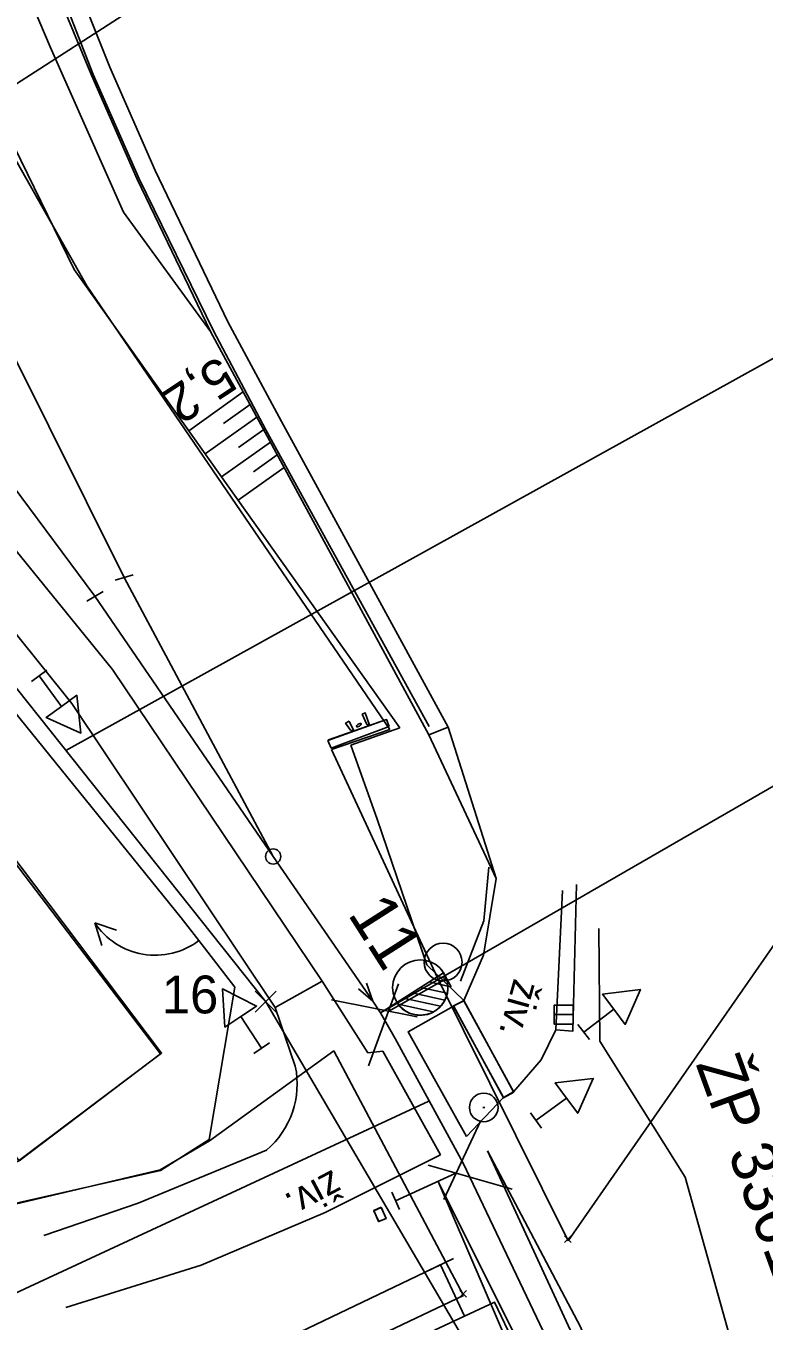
# Model space of a CAD drawing. Extents: x -804166 to -803706, y -1151030 to -1150147.
# Drawn here: x -803897.2 to -803858.2, y -1150515.9 to -1150447.5 of the extents above; entities that cross this region are included whole.
import ezdxf

# ---------------------------------------------------------------- set-up
doc = ezdxf.new("R2010")
doc.units = 0
for name, color, linetype in [('0381KM032-037P - Vrstva 1', 7, 'Continuous'), ('0381KM032-037P - Vrstva 12', 7, 'Continuous'), ('0381KM032-037P - Vrstva 13', 7, 'Continuous'), ('0381KM032-037P - Vrstva 17', 7, 'Continuous'), ('0381KM032-037P - Vrstva 19', 7, 'Continuous'), ('0381KM032-037P - Vrstva 2', 7, 'Continuous'), ('0381KM032-037P - Vrstva 23', 7, 'Continuous'), ('0381KM032-037P - Vrstva 3', 7, 'Continuous'), ('0381KM032-037P - Vrstva 4', 7, 'Continuous'), ('0381KM032-037P - Vrstva 43', 7, 'Continuous'), ('0381KM032-037P - Vrstva 48', 7, 'Continuous'), ('0381KM032-037P - Vrstva 49', 7, 'Continuous'), ('0381KM032-037P - Vrstva 5', 7, 'Continuous'), ('0381KM032-037P - Vrstva 51', 7, 'Continuous'), ('0381KM032-037P - Vrstva 55', 7, 'Continuous'), ('Default', 7, 'Continuous'), ('hran DP - hran DP', 7, 'Continuous'), ('PSR_C2_2_Lomove_body_Vimperk - Vrstva 60', 7, 'Continuous'), ('PSR_C2_2_trasa_Vimperk - Kabelová trasa', 7, 'Continuous'), ('SOPS', 7, 'Continuous'), ('vyt_sit - stávající', 7, 'Continuous')]:
    doc.layers.add(name, color=color, linetype=linetype)

msp = doc.modelspace()

# ---------------------------------------------------------------- linework, layer by layer
at = {"layer": '0381KM032-037P - Vrstva 1'}
msp.add_line((-803901.897, -1150466.329), (-803893.522, -1150477.59), dxfattribs=at)
for points in [[(-804011.14, -1150262.39), (-804005.45, -1150273.41), (-803998.73, -1150284.85), (-803991.51, -1150295.63), (-803978.8, -1150312.77), (-803963.69, -1150332.99), (-803952.21, -1150348.36), (-803946.3, -1150356.39), (-803941.6, -1150363.14), (-803936.71, -1150370.83), (-803932.05, -1150378.84), (-803927.78, -1150386.91), (-803924.06, -1150395.18), (-803920.62, -1150403.65), (-803918.06, -1150410.86), (-803915.07, -1150420.32), (-803912.96, -1150427.25), (-803910.49, -1150435.34), (-803907.334, -1150445.05), (-803903.668, -1150454.381), (-803897.938, -1150464.596), (-803891.973, -1150476.598)], [(-803891.973, -1150476.598), (-803884.106, -1150491.333), (-803878.839, -1150498.97), (-803878.441, -1150499.601)], [(-803893.522, -1150477.59), (-803884.106, -1150491.333), (-803878.839, -1150498.97), (-803878.441, -1150499.601)], [(-803878.441, -1150499.601), (-803877.664, -1150500.946), (-803874.069, -1150507.541)], [(-803874.069, -1150507.541), (-803869.666, -1150516.774), (-803865.801, -1150526.594), (-803862.645, -1150536.71)]]:
    msp.add_lwpolyline(points, dxfattribs=at)
at = {"layer": '0381KM032-037P - Vrstva 12'}
for q in [(-803878.793, -1150510.039), (-803878.397, -1150509.87), (-803878.143, -1150510.457)]:
    msp.add_line((-803878.393, -1150509.855), q, dxfattribs=at)
for points in [[(-803878.788, -1150510.049), (-803878.793, -1150510.039), (-803878.537, -1150510.622), (-803878.523, -1150510.621)], [(-803878.397, -1150509.87), (-803878.788, -1150510.049), (-803878.523, -1150510.621), (-803878.141, -1150510.449), (-803878.397, -1150509.87)], [(-803878.537, -1150510.622), (-803878.143, -1150510.457), (-803878.141, -1150510.449)]]:
    msp.add_lwpolyline(points, dxfattribs=at)
at = {"layer": '0381KM032-037P - Vrstva 13'}
msp.add_lwpolyline([(-803875.883, -1150484.91), (-803874.859, -1150484.495), (-803883.662, -1150468.351), (-803886.496, -1150463.09), (-803890.342, -1150455.103), (-803892.739, -1150449.637), (-803894.892, -1150444.207), (-803895.921, -1150441.276), (-803896.676, -1150438.635), (-803897.147, -1150435.872), (-803897.2, -1150433.432), (-803898.654, -1150433.258), (-803898.54, -1150435.86), (-803897.995, -1150438.863), (-803897.041, -1150441.738), (-803895.987, -1150444.528), (-803893.704, -1150450.064), (-803891.289, -1150455.545), (-803887.412, -1150463.602)], close=True, dxfattribs=at)
at = {"layer": '0381KM032-037P - Vrstva 17'}
msp.add_line((-803888.961, -1150494.568), (-803888.027, -1150495.776), dxfattribs=at)
for points in [[(-803875.87, -1150484.459), (-803884.486, -1150468.8), (-803887.25, -1150463.566), (-803891.192, -1150455.528), (-803893.615, -1150450.032), (-803895.787, -1150444.436), (-803896.9, -1150441.761), (-803897.818, -1150438.885), (-803898.314, -1150435.883), (-803898.256, -1150432.783)], [(-803907.336, -1150471.899), (-803888.961, -1150494.568)], [(-803872.719, -1150491.9), (-803872.971, -1150494.735), (-803874.21, -1150497.92)], [(-803888.027, -1150495.776), (-803886.131, -1150498.244), (-803887.49, -1150506.275), (-803890.053, -1150507.927), (-803899.02, -1150509.954)]]:
    msp.add_lwpolyline(points, dxfattribs=at)
at = {"layer": '0381KM032-037P - Vrstva 19'}
for p, q in [((-803881.212, -1150485.202), (-803878.118, -1150484.104)), ((-803879.404, -1150483.821), (-803879.155, -1150484.356)), ((-803879.155, -1150484.356), (-803879.022, -1150484.392)), ((-803878.118, -1150484.104), (-803877.97, -1150484.474)), ((-803877.97, -1150484.474), (-803881.045, -1150485.616)), ((-803881.045, -1150485.616), (-803881.212, -1150485.202))]:
    msp.add_line(p, q, dxfattribs=at)
for points in [[(-803879.022, -1150484.392), (-803879.242, -1150483.752), (-803879.404, -1150483.821)], [(-803878.118, -1150484.104), (-803878.118, -1150484.104), (-803881.188, -1150485.171), (-803881.212, -1150485.202)], [(-803880.088, -1150484.181), (-803879.836, -1150484.689), (-803880.019, -1150484.664), (-803880.278, -1150484.296), (-803880.088, -1150484.181)]]:
    msp.add_lwpolyline(points, dxfattribs=at)
msp.add_ellipse((-803879.582, -1150484.395), major_axis=(-0.127, -0.08), ratio=0.380929, dxfattribs=at)
at = {"layer": '0381KM032-037P - Vrstva 2'}
for p, q in [((-803878.441, -1150499.601), (-803834.824, -1150474.404)), ((-803892.452, -1150476.741), (-803891.494, -1150476.455)), ((-803891.973, -1150476.598), (-803884.106, -1150491.333)), ((-803893.094, -1150477.331), (-803893.95, -1150477.849)), ((-803877.575, -1150499.045), (-803875.106, -1150497.473)), ((-803875.874, -1150497.962), (-803874.883, -1150498.182)), ((-803875.427, -1150497.677), (-803874.961, -1150497.78)), ((-803877.217, -1150498.817), (-803875.266, -1150499.249)), ((-803876.77, -1150498.532), (-803875.035, -1150498.916)), ((-803876.321, -1150498.247), (-803874.912, -1150498.559)), ((-803877.576, -1150499.046), (-803878.441, -1150499.601)), ((-803877.574, -1150499.046), (-803877.575, -1150499.045)), ((-803877.507, -1150499.136), (-803875.654, -1150499.547))]:
    msp.add_line(p, q, dxfattribs=at)
for points in [[(-803893.522, -1150477.59), (-803884.106, -1150491.333), (-803878.839, -1150498.97), (-803878.441, -1150499.601)], [(-803879.6, -1150498.322), (-803878.839, -1150498.97), (-803879.174, -1150498.028)]]:
    msp.add_lwpolyline(points, dxfattribs=at)
for centre, radius in [((-803884.106, -1150491.333), 0.4), ((-803876.333, -1150498.256), 1.462)]:
    msp.add_circle(centre, radius, dxfattribs=at)
msp.add_arc((-803876.341, -1150498.259), 1.464, 212.53717, 32.49802, dxfattribs=at)
at = {"layer": '0381KM032-037P - Vrstva 23'}
for p, q in [((-803893.152, -1150496.036), (-803893.533, -1150494.83)), ((-803893.533, -1150494.83), (-803893.152, -1150496.036)), ((-803893.533, -1150494.83), (-803892.379, -1150495.228))]:
    msp.add_line(p, q, dxfattribs=at)
msp.add_lwpolyline([(-803897.633, -1150507.469), (-803890, -1150501.72), (-803898.947, -1150489.885)], dxfattribs=at)
msp.add_arc((-803890.335, -1150492.714), 3.834, 213.48969, 307.00957, dxfattribs=at)
at = {"layer": '0381KM032-037P - Vrstva 3'}
msp.add_line((-803903.668, -1150454.381), (-803871.126, -1150433.376), dxfattribs=at)
at = {"layer": '0381KM032-037P - Vrstva 4'}
for p, q in [((-803874.703, -1150498.219), (-803875.193, -1150497.347)), ((-803879.067, -1150502.394), (-803877.487, -1150498.063)), ((-803874.948, -1150497.783), (-803877.999, -1150499.498)), ((-803876.506, -1150499.806), (-803881.027, -1150498.907)), ((-803877.664, -1150500.946), (-803874.069, -1150507.541)), ((-803875.88, -1150504.253), (-803939.777, -1150533.943)), ((-803873.145, -1150505.275), (-803875.086, -1150509.456)), ((-803875.915, -1150507.636), (-803871.486, -1150508.915)), ((-803877.639, -1150509.52), (-803874.454, -1150508.069)), ((-803877.846, -1150509.065), (-803877.432, -1150509.975))]:
    msp.add_line(p, q, dxfattribs=at)
for points in [[(-803872.779, -1150506.875), (-803867.872, -1150516.171), (-803864.004, -1150525.679), (-803860.599, -1150536.286), (-803857.956, -1150547.888), (-803856.113, -1150558.65), (-803855.009, -1150569.422), (-803855.013, -1150580.14), (-803855.681, -1150591.137), (-803857.109, -1150602.102)], [(-803872.779, -1150506.875), (-803868.424, -1150516.34), (-803864.491, -1150525.922), (-803861.191, -1150536.397), (-803858.415, -1150547.949), (-803856.721, -1150558.765), (-803855.706, -1150569.464), (-803855.706, -1150580.041), (-803856.439, -1150591.045), (-803858.016, -1150602.009)], [(-803875.392, -1150508.511), (-803870.942, -1150517.43), (-803867.281, -1150527.019), (-803864.067, -1150537.143), (-803861.546, -1150548.304), (-803859.948, -1150558.943), (-803859.253, -1150569.653), (-803859.085, -1150579.867)], [(-803875.392, -1150508.511), (-803871.454, -1150517.68), (-803867.834, -1150527.236), (-803864.663, -1150537.291), (-803862.152, -1150548.382), (-803860.595, -1150558.999), (-803859.922, -1150569.628), (-803859.947, -1150579.801), (-803860.5, -1150590.58), (-803862.041, -1150601.171)]]:
    msp.add_lwpolyline(points, dxfattribs=at)
at = {"layer": '0381KM032-037P - Vrstva 43'}
for points in [[(-803871.406, -1150503.772), (-803871.943, -1150504.067), (-803874.575, -1150499.234), (-803874.041, -1150498.946), (-803871.406, -1150503.772)], [(-803874.573, -1150499.229), (-803874.026, -1150498.951), (-803871.394, -1150503.78), (-803871.938, -1150504.086), (-803874.573, -1150499.229)], [(-803869.26, -1150499.687), (-803869.26, -1150499.187), (-803868.26, -1150499.187), (-803868.26, -1150500.187), (-803869.26, -1150500.187), (-803869.26, -1150499.687), (-803868.26, -1150499.687)]]:
    msp.add_lwpolyline(points, dxfattribs=at)
msp.add_circle((-803875.129, -1150496.91), 1, dxfattribs=at)
at = {"layer": '0381KM032-037P - Vrstva 48'}
for p, q in [((-803885.686, -1150466.792), (-803888.569, -1150468.841)), ((-803885.327, -1150467.456), (-803886.73, -1150468.454)), ((-803884.967, -1150468.121), (-803887.7, -1150470.063)), ((-803884.607, -1150468.786), (-803885.936, -1150469.73)), ((-803884.248, -1150469.45), (-803886.831, -1150471.286)), ((-803883.888, -1150470.115), (-803885.142, -1150471.006)), ((-803883.529, -1150470.779), (-803885.962, -1150472.509))]:
    msp.add_line(p, q, dxfattribs=at)
at = {"layer": '0381KM032-037P - Vrstva 49'}
for p, q in [((-803880.011, -1150485.455), (-803877.416, -1150484.532)), ((-803875.883, -1150484.91), (-803872.322, -1150492.497)), ((-803868.71, -1150511.374), (-803868.356, -1150511.726)), ((-803868.357, -1150511.373), (-803868.709, -1150511.727)), ((-803874.253, -1150514.268), (-803873.899, -1150514.62)), ((-803873.9, -1150514.267), (-803874.252, -1150514.621))]:
    msp.add_line(p, q, dxfattribs=at)
for points in [[(-803920.94, -1150376.21), (-803910.018, -1150390.511), (-803912.553, -1150396.059), (-803903.866, -1150412.95), (-803903.684, -1150418.644), (-803901.421, -1150428.97), (-803900.537, -1150437.639), (-803895.89, -1150448.56), (-803892.01, -1150457.3), (-803887.412, -1150463.602), (-803875.883, -1150484.91), (-803874.859, -1150484.495), (-803872.322, -1150492.497), (-803872.997, -1150496.546), (-803874.041, -1150498.946)], [(-803877.416, -1150484.532), (-803894.615, -1150460.334), (-803907.648, -1150433.624), (-803908.812, -1150430.908)], [(-803874.041, -1150498.946), (-803875.993, -1150497.05), (-803878.613, -1150489.357), (-803880.011, -1150485.455)], [(-803866.91, -1150495.141), (-803866.848, -1150501.095), (-803862.336, -1150508.281), (-803859.067, -1150519.976)]]:
    msp.add_lwpolyline(points, dxfattribs=at)
at = {"layer": '0381KM032-037P - Vrstva 5'}
for p, q in [((-803875.265, -1150512.897), (-803915.956, -1150532.369)), ((-803874.586, -1150512.578), (-803875.944, -1150513.216))]:
    msp.add_line(p, q, dxfattribs=at)
msp.add_lwpolyline([(-803875.265, -1150512.897), (-803873.991, -1150515.613), (-803875.575, -1150516.356), (-803874.513, -1150518.62), (-803871.345, -1150517.133), (-803872.407, -1150514.87), (-803873.991, -1150515.613)], dxfattribs=at)
at = {"layer": '0381KM032-037P - Vrstva 51'}
for p, q in [((-803896.066, -1150481.493), (-803896.874, -1150482.083)), ((-803881.519, -1150497.913), (-803884.008, -1150499.305)), ((-803879.108, -1150501.711), (-803881.519, -1150497.913)), ((-803884.008, -1150499.305), (-803882.935, -1150502.416)), ((-803868.005, -1150500.208), (-803867.403, -1150501.008)), ((-803885.131, -1150501.736), (-803884.297, -1150501.184)), ((-803870.52, -1150504.875), (-803869.928, -1150505.681))]:
    msp.add_line(p, q, dxfattribs=at)
for points in [[(-803881.519, -1150497.913), (-803892.597, -1150481.46), (-803901.351, -1150470.694), (-803906.021, -1150467.127), (-803910.842, -1150463.746), (-803913.43, -1150460.674), (-803913.908, -1150457.138), (-803915.72, -1150453.288)], [(-803884.008, -1150499.305), (-803894.736, -1150483.244), (-803900.893, -1150475.608)], [(-803896.47, -1150481.788), (-803895.29, -1150483.403), (-803896.098, -1150483.993), (-803894.258, -1150484.816), (-803894.483, -1150482.813), (-803895.29, -1150483.403)], [(-803872.322, -1150492.497), (-803872.997, -1150496.546), (-803874.041, -1150498.946), (-803874.575, -1150499.234), (-803876.979, -1150500.591), (-803873.894, -1150506.131)], [(-803868.09, -1150492.82), (-803868.275, -1150500.556), (-803869.181, -1150500.495), (-803868.824, -1150493.135)], [(-803884.714, -1150501.46), (-803885.817, -1150499.792), (-803884.983, -1150499.24), (-803886.783, -1150498.332), (-803886.651, -1150500.344), (-803885.817, -1150499.792)], [(-803867.704, -1150500.608), (-803866.106, -1150499.406), (-803865.505, -1150500.205), (-803864.707, -1150498.354), (-803866.707, -1150498.607), (-803866.106, -1150499.406)], [(-803869.181, -1150500.495), (-803869.951, -1150502.075), (-803871.406, -1150503.772), (-803871.943, -1150504.067), (-803873.894, -1150506.131)], [(-803875.265, -1150507.099), (-803878.317, -1150501.626), (-803879.108, -1150501.711)], [(-803870.224, -1150505.278), (-803868.612, -1150504.094), (-803868.02, -1150504.899), (-803867.202, -1150503.057), (-803869.205, -1150503.288), (-803868.612, -1150504.094)], [(-803884.454, -1150506.841), (-803891.238, -1150509.65), (-803896.223, -1150511.347)], [(-803895.065, -1150515.152), (-803887.917, -1150512.923), (-803881.363, -1150510.148), (-803875.265, -1150507.099)]]:
    msp.add_lwpolyline(points, dxfattribs=at)
msp.add_ellipse((-803887.406, -1150503.348), major_axis=(0.394, 4.563), ratio=0.996998, start_param=3.930903, end_param=5.00319, dxfattribs=at)
at = {"layer": '0381KM032-037P - Vrstva 55'}
msp.add_lwpolyline([(-803901.34, -1150491.89), (-803905.5, -1150486.41), (-803911.98, -1150477.87), (-803911.71, -1150477.67), (-803912.3, -1150476.91), (-803912.56, -1150477.11), (-803912.92, -1150476.64), (-803914.71, -1150478.01), (-803917.95, -1150480.48), (-803906.42, -1150495.69), (-803897.53, -1150507.41), (-803890.06, -1150501.75), (-803898.96, -1150490.08), (-803901.34, -1150491.89)], dxfattribs=at)
at = {"layer": 'hran DP - hran DP'}
for p, q in [((-803900.76, -1150449.16), (-803893.94, -1150461.19)), ((-803893.94, -1150461.19), (-803877.95, -1150484.62)), ((-803877.95, -1150484.62), (-803881.02, -1150485.69)), ((-803881.02, -1150485.69), (-803875.42, -1150497.74)), ((-803868.53, -1150511.63), (-803856.45, -1150494.27)), ((-803875.42, -1150497.74), (-803868.53, -1150511.63)), ((-803880.9, -1150501.6), (-803887.46, -1150506.35)), ((-803874.06, -1150514.53), (-803880.9, -1150501.6)), ((-803887.46, -1150506.35), (-803890.08, -1150507.89)), ((-803890.08, -1150507.89), (-803899.02, -1150510.01)), ((-803881.88, -1150518.24), (-803874.06, -1150514.53))]:
    msp.add_line(p, q, dxfattribs=at)
at = {"layer": 'PSR_C2_2_Lomove_body_Vimperk - Vrstva 60'}
for p, q in [((-803885.051, -1150499.554), (-803883.951, -1150498.454)), ((-803883.951, -1150499.554), (-803885.051, -1150498.454))]:
    msp.add_line(p, q, dxfattribs=at)
at = {"layer": 'PSR_C2_2_trasa_Vimperk - Kabelová trasa'}
msp.add_line((-803884.501, -1150499.004), (-803870.525, -1150522.783), dxfattribs=at)
msp.add_lwpolyline([(-803884.501, -1150499.004), (-803905.623, -1150472.452), (-803904.414, -1150467.973)], dxfattribs=at)
at = {"layer": 'SOPS'}
msp.add_lwpolyline([(-803895.062, -1150485.728), (-803853.671, -1150462.792), (-803855.715, -1150452.769)], dxfattribs=at)
at = {"layer": 'vyt_sit - stávající'}
msp.add_line((-803873.031, -1150504.591), (-803872.931, -1150504.591), dxfattribs=at)
msp.add_circle((-803872.981, -1150504.591), 0.756, dxfattribs=at)

# ---------------------------------------------------------------- texts
at = {"layer": '0381KM032-037P - Vrstva 2'}
msp.add_text('11', height=2.5, rotation=302.51759, dxfattribs=at).set_placement((-803880.207, -1150494.369))
at = {"layer": '0381KM032-037P - Vrstva 48'}
msp.add_text('5,2', height=2, rotation=213.41624, dxfattribs=at).set_placement((-803886.957, -1150464.841))
at = {"layer": '0381KM032-037P - Vrstva 51'}
for rotation, p in [(254.39036, (-803871.378, -1150497.731)), (207.94807, (-803880.962, -1150507.851))]:
    msp.add_text('živ.', height=1.5, rotation=rotation, dxfattribs=at).set_placement(p)
at = {"layer": 'Default'}
msp.add_text('16', height=2, dxfattribs=at).set_placement((-803889.981, -1150499.623))
at = {"layer": 'vyt_sit - stávající'}
msp.add_text('ŽP 3361', height=2.4, rotation=290, dxfattribs=at).set_placement((-803861.801, -1150502.287))

doc.saveas('drawing.dxf')
